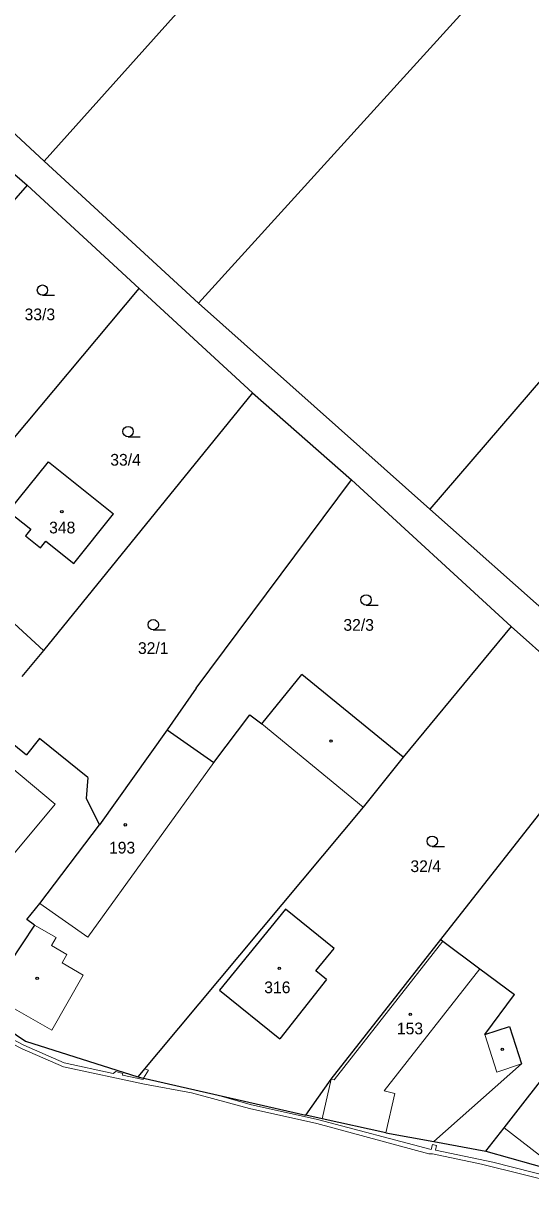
# Model space of a CAD drawing. Extents: x -694609 to -690140, y -1033292 to -1029794.
# Drawn here: x -692481 to -692407.6, y -1031455.4 to -1031285.6 of the extents above; entities that cross this region are included whole.
import ezdxf
from ezdxf.enums import TextEntityAlignment as Align

# ---------------------------------------------------------------- set-up
doc = ezdxf.new("R2010")
doc.units = 0
doc.header["$LTSCALE"] = 0.68
for name, color, linetype, lineweight in [('1', 7, 'Continuous', 25), ('13', 7, 'Continuous', 13), ('3', 7, 'Continuous', 25), ('4', 7, 'Continuous', 13), ('5', 7, 'Continuous', 25)]:
    doc.layers.add(name, color=color, linetype=linetype, lineweight=lineweight)
doc.layers.add('2', color=7, linetype='Continuous')

msp = doc.modelspace()

# ---------------------------------------------------------------- linework, layer by layer
at = {"layer": '1'}
for p, q in [((-692321.26, -1031130.11), (-692478, -1031305.52)), ((-692417.34, -1031283.88), (-692455.67, -1031326.12)), ((-692478, -1031305.52), (-692497.74, -1031287.3)), ((-692497.63, -1031294.11), (-692480.48, -1031309)), ((-692455.67, -1031326.12), (-692478, -1031305.52)), ((-692480.48, -1031309), (-692494.7, -1031325.3)), ((-692464.25, -1031323.97), (-692480.48, -1031309)), ((-692389.22, -1031317.57), (-692422.13, -1031355.95)), ((-692489.24, -1031353.84), (-692464.25, -1031323.97)), ((-692447.83, -1031339.11), (-692464.25, -1031323.97)), ((-692422.13, -1031355.95), (-692455.67, -1031326.12)), ((-692447.83, -1031339.11), (-692478.12, -1031376.44)), ((-692447.83, -1031339.11), (-692433.51, -1031351.71)), ((-692483.15, -1031356.28), (-692477.39, -1031349.09)), ((-692477.39, -1031349.09), (-692467.95, -1031356.65)), ((-692455.97, -1031381.87), (-692433.51, -1031351.71)), ((-692433.51, -1031351.71), (-692410.37, -1031372.97)), ((-692483.15, -1031356.28), (-692479.95, -1031358.84)), ((-692473.71, -1031363.84), (-692467.95, -1031356.65)), ((-692366.85, -1031405.11), (-692422.13, -1031355.95)), ((-692495.08, -1031360.83), (-692478.12, -1031376.44)), ((-692478.55, -1031361.56), (-692477.77, -1031360.59)), ((-692477.77, -1031360.59), (-692473.71, -1031363.84)), ((-692395.42, -1031386.28), (-692410.37, -1031372.97)), ((-692478.12, -1031376.44), (-692481.25, -1031380.18)), ((-692446.49, -1031387.07), (-692440.69, -1031379.92)), ((-692455.97, -1031381.87), (-692460.21, -1031387.94)), ((-692486.59, -1031386.68), (-692480.58, -1031391.53)), ((-692453.44, -1031392.67), (-692448.2, -1031385.77)), ((-692448.2, -1031385.77), (-692446.49, -1031387.07)), ((-692420.58, -1031418.3), (-692395.42, -1031386.28)), ((-692460.21, -1031387.94), (-692469.98, -1031401.71)), ((-692460.21, -1031387.94), (-692453.44, -1031392.67)), ((-692478.7, -1031389.2), (-692480.58, -1031391.53)), ((-692471.69, -1031394.85), (-692478.7, -1031389.2)), ((-692426, -1031391.88), (-692431.83, -1031399.12)), ((-692471.69, -1031394.85), (-692471.9, -1031397.86)), ((-692471.9, -1031397.86), (-692469.98, -1031401.71)), ((-692431.83, -1031399.12), (-692464.42, -1031438.22)), ((-692478.64, -1031413.1), (-692469.98, -1031401.71)), ((-692480.5, -1031415.43), (-692478.64, -1031413.1)), ((-692443.05, -1031413.9), (-692452.59, -1031425.67)), ((-692436.02, -1031419.6), (-692443.05, -1031413.9)), ((-692479.41, -1031416.26), (-692480.5, -1031415.43)), ((-692479.41, -1031416.26), (-692486.02, -1031426.22)), ((-692438.66, -1031422.86), (-692436.02, -1031419.6)), ((-692436.43, -1031438.54), (-692420.58, -1031418.3)), ((-692420.58, -1031418.3), (-692420.25, -1031418.54)), ((-692420.25, -1031418.54), (-692414.89, -1031422.54)), ((-692437.11, -1031424.12), (-692438.66, -1031422.86)), ((-692414.89, -1031422.54), (-692409.87, -1031426.28)), ((-692411.4, -1031445.59), (-692393.22, -1031422.18)), ((-692437.11, -1031424.12), (-692443.89, -1031432.72)), ((-692452.59, -1031425.67), (-692443.89, -1031432.72)), ((-692414.19, -1031432.07), (-692409.87, -1031426.28)), ((-692487.58, -1031428.44), (-692480.73, -1031433.04)), ((-692414.19, -1031432.07), (-692410.6, -1031430.93)), ((-692410.6, -1031430.93), (-692408.89, -1031436.35)), ((-692480.73, -1031433.04), (-692464.42, -1031438.22)), ((-692408.89, -1031436.35), (-692421.59, -1031447.6)), ((-692464.42, -1031438.22), (-692440.13, -1031443.75)), ((-692440.13, -1031443.75), (-692436.43, -1031438.54)), ((-692437.73, -1031444.29), (-692440.13, -1031443.75)), ((-692428.52, -1031446.35), (-692437.73, -1031444.29)), ((-692428.52, -1031446.35), (-692421.59, -1031447.6)), ((-692414.04, -1031448.99), (-692411.4, -1031445.59)), ((-692421.59, -1031447.6), (-692414.04, -1031448.99)), ((-692414.04, -1031448.99), (-692395.05, -1031454.33))]:
    msp.add_line(p, q, dxfattribs=at)
for points in [[(-692479.95, -1031358.84), (-692480.73, -1031359.82), (-692478.55, -1031361.56)], [(-692410.37, -1031372.97), (-692426, -1031391.88), (-692440.69, -1031379.92)]]:
    msp.add_lwpolyline(points, dxfattribs=at)
at = {"layer": '13'}
for points in [[(-692616.25, -1031341.28), (-692607.49, -1031351.91), (-692604.81, -1031354.65), (-692596.87, -1031361.63), (-692586.63, -1031370.38), (-692585.23, -1031371.29), (-692584.59, -1031371.43), (-692575.5, -1031376.96), (-692543.42, -1031396.45), (-692539.51, -1031398.51), (-692516.26, -1031412.35), (-692503.12, -1031420.19), (-692488.88, -1031428.73), (-692489.19, -1031430.04), (-692481.21, -1031434.16), (-692475.21, -1031436.76), (-692463.45, -1031439.27), (-692456.68, -1031440.53), (-692448.29, -1031442.79)], [(-692398.23, -1031454.37), (-692413.03, -1031450.59), (-692421.35, -1031448.83), (-692421.19, -1031448.15), (-692421.77, -1031448.01), (-692421.96, -1031448.76), (-692438.4, -1031444.42), (-692448.15, -1031442.21), (-692453.03, -1031440.81), (-692463.03, -1031438.54), (-692463.62, -1031438.4), (-692463.65, -1031438.62), (-692466.67, -1031437.99), (-692466.61, -1031437.74), (-692467.63, -1031437.44), (-692468.03, -1031437.74), (-692475.09, -1031436.18), (-692480.95, -1031433.62), (-692488.49, -1031429.72)], [(-692448.29, -1031442.79), (-692438.54, -1031445), (-692422.28, -1031449.37), (-692421.75, -1031449.36), (-692414.65, -1031450.86), (-692396.4, -1031455.42)]]:
    msp.add_lwpolyline(points, dxfattribs=at)
msp.add_lwpolyline([(-692463.46, -1031437.07), (-692464.42, -1031438.22), (-692463.62, -1031438.4), (-692462.88, -1031437.25)], close=True, dxfattribs=at)
at = {"layer": '3'}
for p, q in [((-692478.253, -1031324.96), (-692476.503, -1031324.96)), ((-692465.853, -1031345.46), (-692464.103, -1031345.46)), ((-692431.393, -1031369.85), (-692429.643, -1031369.85)), ((-692462.203, -1031373.44), (-692460.453, -1031373.44)), ((-692421.803, -1031404.83), (-692420.053, -1031404.83))]:
    msp.add_line(p, q, dxfattribs=at)
for centre in [(-692478.2529, -1031324.2098), (-692465.8529, -1031344.7098), (-692431.3929, -1031369.0998), (-692462.2029, -1031372.6898), (-692421.8029, -1031404.0798)]:
    msp.add_circle(centre, 0.75, dxfattribs=at)
at = {"layer": '4'}
for p, q in [((-692431.83, -1031399.12), (-692446.49, -1031387.07)), ((-692453.44, -1031392.67), (-692471.67, -1031417.96)), ((-692478.64, -1031413.1), (-692471.67, -1031417.96)), ((-692479.41, -1031416.26), (-692476.27, -1031418.02)), ((-692476.27, -1031418.02), (-692476.94, -1031419.18)), ((-692476.94, -1031419.18), (-692474.71, -1031420.47)), ((-692436, -1031438.64), (-692420.25, -1031418.54)), ((-692474.71, -1031420.47), (-692475.42, -1031421.7)), ((-692475.42, -1031421.7), (-692472.34, -1031423.48)), ((-692428.78, -1031440.26), (-692414.89, -1031422.54)), ((-692472.34, -1031423.48), (-692476.91, -1031431.45)), ((-692486.02, -1031426.22), (-692476.91, -1031431.45)), ((-692414.19, -1031432.07), (-692412.46, -1031437.52)), ((-692408.89, -1031436.35), (-692412.46, -1031437.52)), ((-692437.73, -1031444.29), (-692436.43, -1031438.54)), ((-692436, -1031438.64), (-692436.43, -1031438.54)), ((-692411.4, -1031445.59), (-692406.25, -1031449.58))]:
    msp.add_line(p, q, dxfattribs=at)
for points in [[(-692483.35, -1031407.07), (-692476.39, -1031398.68), (-692486.32, -1031390.45)], [(-692428.52, -1031446.35), (-692427.23, -1031440.61), (-692428.78, -1031440.26)]]:
    msp.add_lwpolyline(points, dxfattribs=at)
at = {"layer": '5'}
for centre in [(-692475.4468, -1031356.3292), (-692436.4568, -1031389.5592), (-692466.2568, -1031401.6992), (-692443.9568, -1031422.4992), (-692479.0168, -1031423.9492), (-692424.9868, -1031429.1692), (-692411.6568, -1031434.2192)]:
    msp.add_circle(centre, 0.175, dxfattribs=at)

# ---------------------------------------------------------------- texts
at = {"layer": '2'}
for s, p in [('33/3', (-692478.629, -1031328.575)), ('33/4', (-692466.219, -1031349.645)), ('348', (-692475.389, -1031359.465)), ('32/3', (-692432.459, -1031373.575)), ('32/1', (-692462.209, -1031376.935)), ('193', (-692466.719, -1031405.855)), ('32/4', (-692422.749, -1031408.545)), ('316', (-692444.239, -1031426.095)), ('153', (-692425.029, -1031432.055))]:
    msp.add_text(s, height=1.7, dxfattribs=at).set_placement(p, align=Align.CENTER)

doc.saveas('drawing.dxf')
